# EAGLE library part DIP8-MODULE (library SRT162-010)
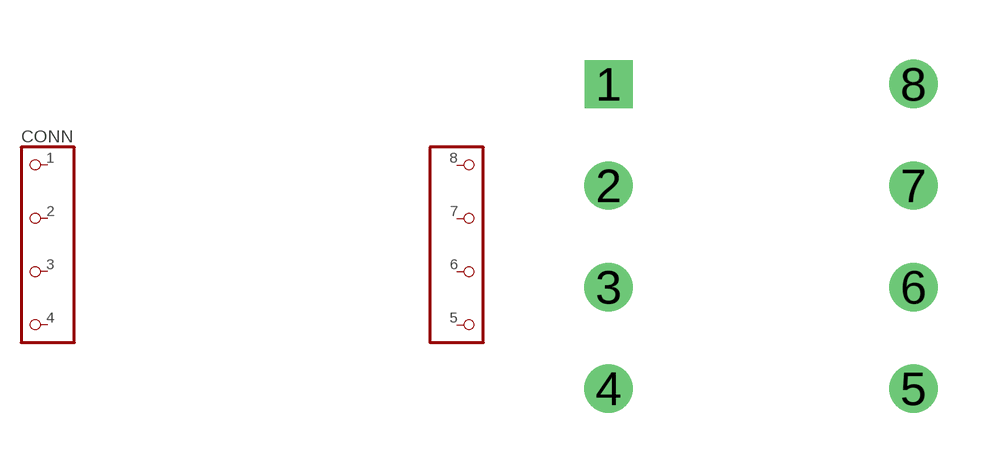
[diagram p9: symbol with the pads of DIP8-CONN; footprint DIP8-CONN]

Designator prefix CONN

## DIP8-MODULE  [DIP8-CONN]
1  1  pas
2  2  pas
3  3  pas
4  4  pas
5  5  pas
6  6  pas
7  7  pas
8  8  pas

## Footprint DIP8-CONN (pad centres in mm)
drill 0.7 square: 1 -3.81,3.81
drill 0.7 round: 2 -3.81,1.27; 3 -3.81,-1.27; 4 -3.81,-3.81; 5 3.81,-3.81; 6 3.81,-1.27; 7 3.81,1.27; 8 3.81,3.81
